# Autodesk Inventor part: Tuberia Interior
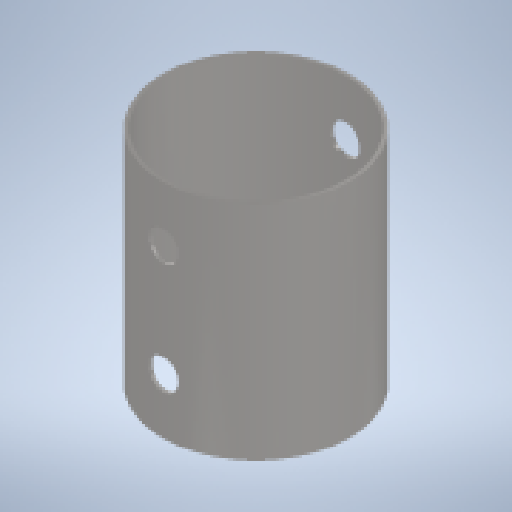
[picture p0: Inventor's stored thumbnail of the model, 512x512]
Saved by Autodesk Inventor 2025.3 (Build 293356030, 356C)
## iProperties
Created: 2025-10
Part Number: Tuberia Interior
Material: Hierro, fundido
Document SubType Name: Modeling
Designer: Asus
Density: 7.15 g/cm^3
Appearance: Inoxidable - Bruñido
Author: Asus
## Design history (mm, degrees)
sketch "Boceto1"
  geometry: C1 r 84.138 at (0, 0); C2 r 77.028 at (0, 0); 1 further point
  constraints: 2 centre point, 2 coincident
  dimensions: "d0" = 168.275 diameter of C1; "d1" = 7.11 radial gap between concentric circles of C1 C2
extrude "Extrusión1" new body sketch "Boceto1" distance "d2" = 200; taper "d3" = 0 deg
sketch "Boceto2"
  geometry: C1 r 81 at (0, 0); 1 further point
  constraints: 1 centre point, 1 coincident
  dimensions: "d4" = 162 diameter of C1
extrude "Extrusión2" cut sketch "Boceto2" extent not by distance; stored distance "d5" = 200; taper "d6" = 0 deg
node "Plano de trabajo1"
sketch "Boceto3"
  geometry: L1 (0, 240)-(0, -40) reference; L2 (84.138, 200)-(-84.138, 200) reference; L3 (84.138, 0)-(-84.138, 0) reference; 3 further points
  dimensions: "d7" = 0 distance from line of L1 point (0, 150); "d8" = 0 distance from line of L1 point (0, 50) (computed from d7); "d9" = 50 distance from line of point (0, 150) L2 (= d10); "d10" = 50 distance from line of L3 point (0, 50); "d11" = 100 distance of point (0, 50) point (0, 150) (derived)
hole "Agujero1" sketch "Boceto3" at (0, 150), (0, 50) diameter "d12" = 27; stored, may be unused: countersink angle "d16" = 90 deg, drill point angle "d18" = 118 deg; dims "d13" = 6, "d14" = 4, "d15" = 2, "d17" = 8
node "Sólido1"
